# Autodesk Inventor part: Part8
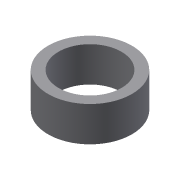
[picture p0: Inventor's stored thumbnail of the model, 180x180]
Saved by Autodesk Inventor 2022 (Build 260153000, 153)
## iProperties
Created: 2002-01
Part Number: Part8
Document SubType Name: Modeling
Designer: ***
Density: 1 g/cm^3
Material: Generic
Appearance: Default
Control State: 0
Master: False
Checked Out: False
Shininess: 77.0
Length Units: 11269
Angle Units: 11279
Time Units: 11290
Mass Units: 11283
Length Display Precision: 3
Angle Display Precision: 2
Density: 0.0
Volumn: 0.0
Area: 0.0
PropertySet Name: Model Information
Author: ***
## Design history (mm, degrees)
sketch "Sketch1"
  geometry: C1 r 30 at (0, 0); C2 r 22.5 at (0, 0)
  constraints: 2 centre point, 1 coincident
  dimensions: "d0" = 60 diameter of C1; "d1" = 45 diameter of C2
extrude "Extrusion1" new body sketch "Sketch1" distance "d2" = 25; taper "d3" = 0 deg
body "Solid1"
